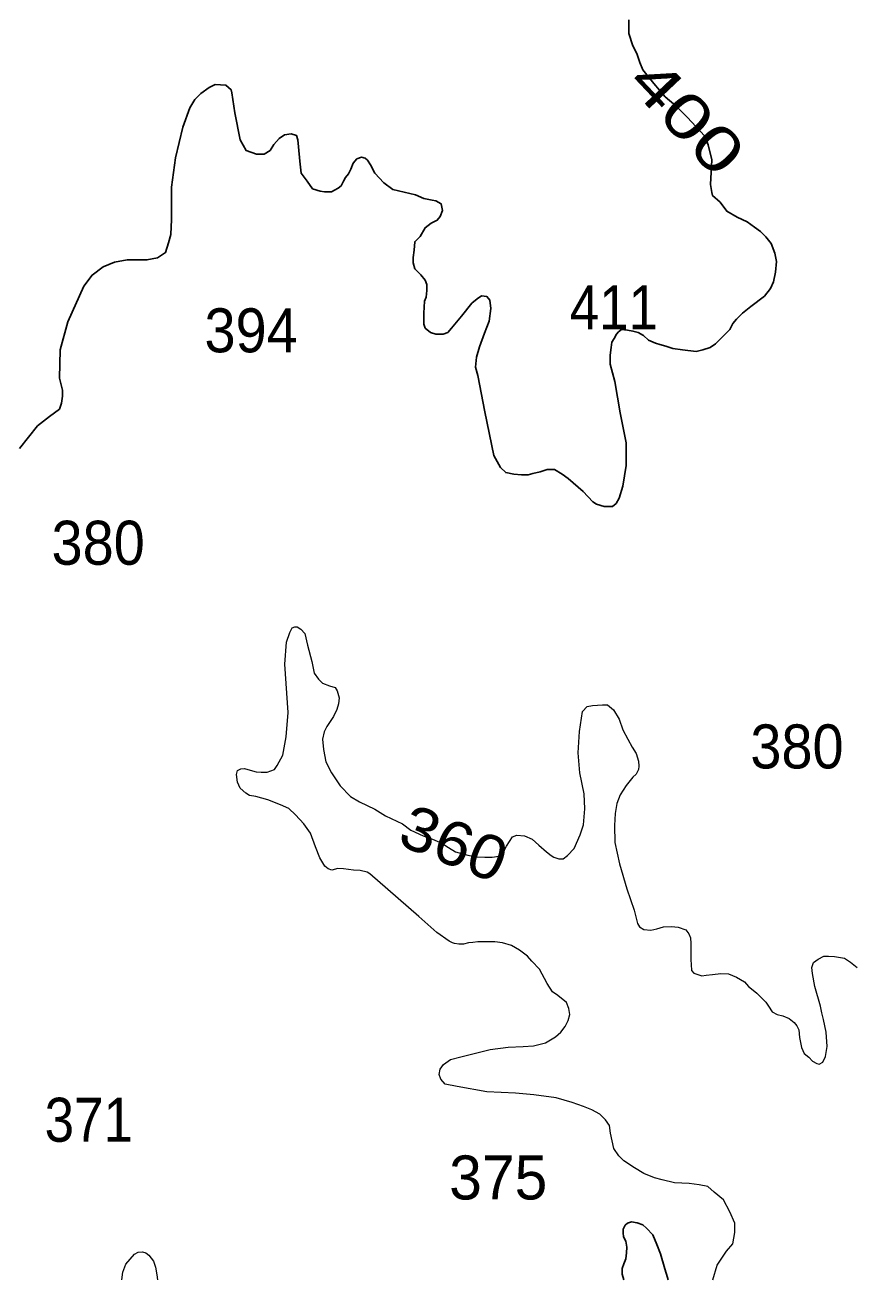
# Model space of a CAD drawing. Extents: x 445.4 to 500, y 8728.7 to 8784.
# Drawn here: x 494.73 to 497.752, y 8728.719 to 8733.282 of the extents above; entities that cross this region are included whole.
import ezdxf
from ezdxf.enums import TextEntityAlignment as Align

# ---------------------------------------------------------------- set-up
doc = ezdxf.new("R2010")
doc.units = 0
doc.header["$LTSCALE"] = 0.064
doc.layers.add('1', color=7, linetype='Continuous', lineweight=25)
doc.layers.add('2', color=7, linetype='Continuous', lineweight=13)
doc.layers.add('21', color=7, linetype='Continuous')
doc.layers.add('61', color=7, linetype='Continuous')

msp = doc.modelspace()

# ---------------------------------------------------------------- linework, layer by layer
at = {"layer": '1'}
for points in [[(496.9267, 8733.301), (496.9267, 8733.2516), (496.9411, 8733.2062), (496.9548, 8733.1789), (496.9657, 8733.1462), (496.9766, 8733.1189), (497.0176, 8733.0698), (497.0586, 8733.0207), (497.0969, 8732.988), (497.1378, 8732.9471), (497.1706, 8732.9116), (497.2007, 8732.8789), (497.2144, 8732.8461), (497.228, 8732.7916), (497.2226, 8732.7016), (497.2278, 8732.6729), (497.2305, 8732.662), (497.2578, 8732.6375), (497.2824, 8732.6048), (497.3207, 8732.5829), (497.3562, 8732.5666), (497.3835, 8732.5475), (497.4054, 8732.5311), (497.4245, 8732.512), (497.4437, 8732.4875), (497.4573, 8732.452), (497.4628, 8732.422), (497.4601, 8732.3838), (497.4519, 8732.3484), (497.4409, 8732.3238), (497.4191, 8732.2966), (497.3699, 8732.2584), (497.3398, 8732.2347), (497.3179, 8732.2129), (497.3043, 8732.1965), (497.2933, 8732.1747), (497.266, 8732.1474), (497.2414, 8732.1229), (497.2223, 8732.1093), (497.195, 8732.1011), (497.1704, 8732.0956), (497.1212, 8732.1011), (497.0857, 8732.1065), (497.0611, 8732.1147), (497.0392, 8732.1202), (497.0228, 8732.1256), (496.9982, 8732.1365), (496.9791, 8732.1529), (496.96, 8732.1638), (496.9408, 8732.1693), (496.9217, 8732.172), (496.8998, 8732.1747), (496.8889, 8732.1665), (496.8807, 8732.1584), (496.8725, 8732.142), (496.8643, 8732.1284), (496.8616, 8732.1093), (496.8588, 8732.082), (496.8588, 8732.0493), (496.8752, 8731.9865), (496.8944, 8731.872), (496.9162, 8731.7629), (496.9162, 8731.6811), (496.9046, 8731.6055), (496.891, 8731.5619), (496.8801, 8731.5428), (496.8664, 8731.5319), (496.8363, 8731.5319), (496.809, 8731.54), (496.7953, 8731.5482), (496.7598, 8731.5864), (496.7052, 8731.6328), (496.6833, 8731.6491), (496.656, 8731.6655), (496.6286, 8731.6655), (496.6041, 8731.6573), (496.5767, 8731.6519), (496.5603, 8731.6464), (496.5357, 8731.6464), (496.5084, 8731.6491), (496.4784, 8731.6546), (496.4592, 8731.6737), (496.4346, 8731.7173), (496.4018, 8731.8755), (496.3772, 8732.0083), (496.369, 8732.0383), (496.3717, 8732.0738), (496.3826, 8732.112), (496.4017, 8732.1611), (496.4181, 8732.2047), (496.4236, 8732.2511), (496.4209, 8732.2811), (496.4099, 8732.2947), (496.3908, 8732.2974)], [(496.3908, 8732.2974), (496.3744, 8732.2865), (496.3553, 8732.2702), (496.317, 8732.2238), (496.2815, 8732.1802), (496.2678, 8732.1638), (496.2514, 8732.1583), (496.2241, 8732.1583), (496.205, 8732.1638), (496.1859, 8732.1802), (496.1804, 8732.1938), (496.1804, 8732.2347), (496.1831, 8732.2784), (496.1886, 8732.292), (496.1913, 8732.3165), (496.1913, 8732.3384), (496.1859, 8732.3547), (496.1695, 8732.3738), (496.1476, 8732.3956), (496.1421, 8732.4175), (496.1421, 8732.4365), (496.1449, 8732.4638), (496.1476, 8732.4938), (496.1667, 8732.5129), (496.1858, 8732.5447), (496.2076, 8732.5611), (496.2295, 8732.572), (496.2404, 8732.5857), (496.2486, 8732.6075), (496.2432, 8732.632), (496.224, 8732.6429), (496.2104, 8732.6457), (496.1803, 8732.6511), (496.1502, 8732.6647), (496.0683, 8732.6838), (496.0355, 8732.7084), (496.0027, 8732.7438), (495.9863, 8732.7738), (495.9754, 8732.7902), (495.9672, 8732.7984), (495.9535, 8732.8011), (495.9371, 8732.7957), (495.9234, 8732.7793), (495.9152, 8732.7575), (495.907, 8732.7411), (495.8961, 8732.7275), (495.8879, 8732.7138), (495.8797, 8732.6975), (495.8688, 8732.6893), (495.8551, 8732.6811), (495.8442, 8732.6757), (495.8196, 8732.6757), (495.8032, 8732.6784), (495.7759, 8732.6866), (495.7567, 8732.7138), (495.7349, 8732.7438), (495.7294, 8732.7875), (495.7251, 8732.8395), (495.7224, 8732.8641), (495.7169, 8732.8804), (495.6978, 8732.8859), (495.6732, 8732.8832), (495.6541, 8732.8695), (495.635, 8732.8477), (495.6213, 8732.8259), (495.5994, 8732.8122), (495.5721, 8732.8122), (495.5339, 8732.8259), (495.512, 8732.8641), (495.4929, 8732.9622), (495.4819, 8733.0359), (495.4792, 8733.0468), (495.4601, 8733.0632), (495.4218, 8733.0659), (495.4, 8733.055), (495.3699, 8733.0332), (495.348, 8733.0113), (495.3289, 8732.9813), (495.3043, 8732.9104), (495.277, 8732.7986), (495.2633, 8732.6922), (495.2633, 8732.575), (495.2606, 8732.5204), (495.2524, 8732.4904), (495.2415, 8732.4549), (495.2114, 8732.4359), (495.1731, 8732.4277), (495.1021, 8732.4277), (495.0556, 8732.4195), (495.0146, 8732.4031), (494.9737, 8732.3731), (494.9436, 8732.3322), (494.8852, 8732.2023), (494.8578, 8732.1014), (494.8551, 8731.9978), (494.866, 8731.9541), (494.866, 8731.9323), (494.8633, 8731.9077), (494.8551, 8731.8859), (494.8196, 8731.8587), (494.7753, 8731.8246)], [(494.7753, 8731.8246), (494.7425, 8731.7837), (494.7097, 8731.7428)], [(496.9084, 8728.7196), (496.9015, 8728.7399), (496.9015, 8728.7609), (496.9082, 8728.7775), (496.9149, 8728.7964), (496.9182, 8728.8174), (496.9193, 8728.8384), (496.9149, 8728.8606), (496.9071, 8728.8761), (496.906, 8728.8904), (496.906, 8728.9037), (496.9126, 8728.9181), (496.9215, 8728.9259), (496.9359, 8728.9303), (496.957, 8728.927), (496.977, 8728.9192), (496.9903, 8728.907), (497.0135, 8728.8838), (497.028, 8728.8484), (497.0413, 8728.8141), (497.0568, 8728.7598), (497.0668, 8728.7277), (497.0697, 8728.7196)]]:
    msp.add_lwpolyline(points, dxfattribs=at)
at = {"layer": '2'}
for points in [[(495.5288, 8730.5792), (495.5489, 8730.5732), (495.571, 8730.5672), (495.589, 8730.5652), (495.6111, 8730.5652), (495.6372, 8730.5752), (495.6472, 8730.5892), (495.6673, 8730.6273), (495.6793, 8730.6934), (495.6874, 8730.7822), (495.6753, 8730.9584), (495.6814, 8731.0377), (495.6934, 8731.0737), (495.7014, 8731.0897), (495.7115, 8731.0937), (495.7195, 8731.0937), (495.7335, 8731.0857), (495.7476, 8731.0697), (495.7576, 8731.0277), (495.7737, 8730.9676), (495.7817, 8730.9255), (495.7977, 8730.9035), (495.8118, 8730.8895), (495.8379, 8730.8795), (495.8579, 8730.8735), (495.8659, 8730.8614), (495.872, 8730.8354), (495.87, 8730.8134), (495.8639, 8730.7933), (495.8519, 8730.7673), (495.8281, 8730.7317), (495.8181, 8730.7117), (495.8121, 8730.6857), (495.8161, 8730.6476), (495.8241, 8730.6036), (495.8442, 8730.5635), (495.8763, 8730.5155), (495.9144, 8730.4774), (495.9465, 8730.4574), (496.0027, 8730.4313), (496.0408, 8730.4073), (496.103, 8730.3773), (496.1337, 8730.3542), (496.1778, 8730.3342), (496.2059, 8730.3242), (496.244, 8730.3081), (496.2701, 8730.2921), (496.2962, 8730.2761), (496.3403, 8730.2641), (496.3724, 8730.2581), (496.4025, 8730.2561), (496.4286, 8730.2561), (496.4527, 8730.2601), (496.4667, 8730.2701), (496.4808, 8730.2961), (496.5029, 8730.3302), (496.5189, 8730.3362), (496.547, 8730.3342), (496.5751, 8730.3222), (496.5992, 8730.3001), (496.6272, 8730.2761), (496.6433, 8730.2621), (496.6533, 8730.2561), (496.6714, 8730.2501), (496.6874, 8730.2501), (496.7035, 8730.2621), (496.7276, 8730.2881), (496.7496, 8730.3382), (496.7617, 8730.3742), (496.7657, 8730.4323), (496.7637, 8730.4864), (496.7476, 8730.5625), (496.7421, 8730.6358), (496.7461, 8730.7139), (496.7581, 8730.786), (496.7742, 8730.804), (496.7942, 8730.808), (496.8304, 8730.81), (496.8484, 8730.81), (496.8705, 8730.792), (496.8906, 8730.758), (496.9046, 8730.7199), (496.9227, 8730.6859), (496.9387, 8730.6558), (496.9528, 8730.6338), (496.9608, 8730.6058), (496.9628, 8730.5877), (496.9608, 8730.5757), (496.9528, 8730.5577), (496.9407, 8730.5477), (496.9166, 8730.5176), (496.8946, 8730.4836), (496.8825, 8730.4515), (496.8765, 8730.4155), (496.8745, 8730.3714), (496.8747, 8730.3099), (496.8927, 8730.2318), (496.9188, 8730.1417), (496.9449, 8730.0636), (496.9574, 8730.015), (496.9652, 8730.0034)], [(497.2322, 8728.7197), (497.2471, 8728.7727), (497.2808, 8728.8244), (497.3041, 8728.8502), (497.3118, 8728.8916), (497.3118, 8728.9252), (497.2937, 8728.9665), (497.2704, 8729.0105), (497.2368, 8729.0389), (497.2135, 8729.0596), (497.1824, 8729.0647), (497.1461, 8729.0699), (497.0918, 8729.0725), (497.0478, 8729.0828), (497.0193, 8729.0906), (496.9804, 8729.1061), (496.9468, 8729.1268), (496.9079, 8729.1526), (496.8898, 8729.1707), (496.8717, 8729.1966), (496.8596, 8729.253), (496.8557, 8729.2807), (496.8408, 8729.3016), (496.8209, 8729.3224), (496.7921, 8729.3382), (496.7614, 8729.3501), (496.7197, 8729.365), (496.6621, 8729.3818), (496.5805, 8729.3927), (496.5133, 8729.3988), (496.4093, 8729.4034), (496.3023, 8729.4232), (496.258, 8729.4309), (496.2427, 8729.4492), (496.2366, 8729.466), (496.2397, 8729.4858), (496.2519, 8729.5026), (496.2779, 8729.5209), (496.3146, 8729.53), (496.4214, 8729.5573), (496.487, 8729.566), (496.5416, 8729.5682), (496.5788, 8729.5704), (496.6225, 8729.5813), (496.6596, 8729.6031), (496.6793, 8729.6205), (496.6946, 8729.6402), (496.7056, 8729.662), (496.7121, 8729.6838), (496.7077, 8729.7056), (496.699, 8729.7275), (496.6684, 8729.7536), (496.6487, 8729.7667), (496.629, 8729.7973), (496.6006, 8729.8497), (496.5731, 8729.8786), (496.5571, 8729.8967), (496.529, 8729.9187), (496.4989, 8729.9347), (496.4668, 8729.9447), (496.4387, 8729.9487), (496.4226, 8729.9487), (496.4066, 8729.9487), (496.3925, 8729.9487), (496.3765, 8729.9487), (496.3584, 8729.9467), (496.3424, 8729.9447), (496.3243, 8729.9407), (496.3083, 8729.9407), (496.2922, 8729.9427), (496.2842, 8729.9447), (496.2722, 8729.9507), (496.228, 8729.9828), (496.1618, 8730.0409), (496.0494, 8730.139), (495.9845, 8730.1957), (495.9745, 8730.2017), (495.9484, 8730.2077), (495.9243, 8730.2097), (495.8882, 8730.2137), (495.8682, 8730.2157), (495.8461, 8730.2097), (495.8321, 8730.2137), (495.82, 8730.2238), (495.802, 8730.2538), (495.7859, 8730.2939), (495.7678, 8730.3439), (495.7438, 8730.378), (495.7137, 8730.41), (495.6893, 8730.433), (495.6592, 8730.447), (495.6131, 8730.4651), (495.569, 8730.4771), (495.5469, 8730.4811), (495.5328, 8730.4891), (495.5128, 8730.5071), (495.5028, 8730.5292), (495.4987, 8730.5572), (495.5028, 8730.5712), (495.5148, 8730.5772), (495.5288, 8730.5792)], [(496.9652, 8730.0034), (496.9807, 8729.9931), (497.0065, 8729.9905), (497.0285, 8729.9957), (497.0518, 8730.0034), (497.0815, 8730.0047), (497.106, 8730.0021), (497.1332, 8729.9918), (497.1448, 8729.9776), (497.15, 8729.9634), (497.1513, 8729.9428), (497.1513, 8729.9054), (497.1513, 8729.8834), (497.1526, 8729.8667), (497.1541, 8729.8441), (497.1631, 8729.8351), (497.1916, 8729.8247), (497.2071, 8729.8273), (497.2303, 8729.8299), (497.2601, 8729.8338), (497.2885, 8729.8325), (497.3182, 8729.8196), (497.3466, 8729.8028), (497.3609, 8729.786), (497.3841, 8729.768), (497.3919, 8729.7615), (497.4048, 8729.7486), (497.4242, 8729.7293), (497.4345, 8729.7151), (497.4474, 8729.6945), (497.4655, 8729.6841), (497.4862, 8729.679), (497.5095, 8729.6699), (497.5275, 8729.6558), (497.5366, 8729.6429), (497.5443, 8729.6287), (497.5469, 8729.6003), (497.5538, 8729.5638), (497.5642, 8729.5431), (497.581, 8729.5289), (497.5939, 8729.5148), (497.6094, 8729.5057), (497.6184, 8729.5044), (497.6314, 8729.5109), (497.6417, 8729.5315), (497.6469, 8729.5676), (497.6443, 8729.6205), (497.6339, 8729.6657), (497.6275, 8729.6902), (497.6236, 8729.7147), (497.6031, 8729.7861), (497.594, 8729.8338), (497.5914, 8729.8558), (497.5979, 8729.8738), (497.6147, 8729.8854), (497.6354, 8729.897), (497.6522, 8729.897), (497.6741, 8729.8957), (497.7103, 8729.8893), (497.7323, 8729.8751), (497.7568, 8729.8558)], [(495.0821, 8728.7194), (495.086, 8728.7475), (495.0969, 8728.7769), (495.1122, 8728.7954), (495.1285, 8728.8128), (495.1416, 8728.8205), (495.1569, 8728.8215), (495.17, 8728.8183), (495.1809, 8728.8096), (495.1973, 8728.7878), (495.2049, 8728.766), (495.2092, 8728.7377), (495.2117, 8728.7194)]]:
    msp.add_lwpolyline(points, dxfattribs=at)

# ---------------------------------------------------------------- texts
at = {"layer": '21'}
for s, width, p in [('411', 0.9, (496.7109, 8732.1753)), ('394', 0.95, (495.3827, 8732.092)), ('380', 0.95, (494.8265, 8731.3197)), ('380', 0.95, (497.3681, 8730.5791)), ('371', 0.9, (494.8013, 8729.2218))]:
    msp.add_text(s, height=0.16, dxfattribs=dict(at, width=width)).set_placement(p)
msp.add_text('375', height=0.16, dxfattribs=at).set_placement((496.2727, 8729.0119))
at = {"layer": '61'}
for s, rotation, width, p in [('400', 313.401, 1.35, (497.0807, 8732.8938)), ('360', 338.391, 1.1, (496.2608, 8730.2324))]:
    msp.add_text(s, height=0.16, rotation=rotation, dxfattribs=dict(at, width=width)).set_placement(p, align=Align.CENTER)

doc.saveas('drawing.dxf')
